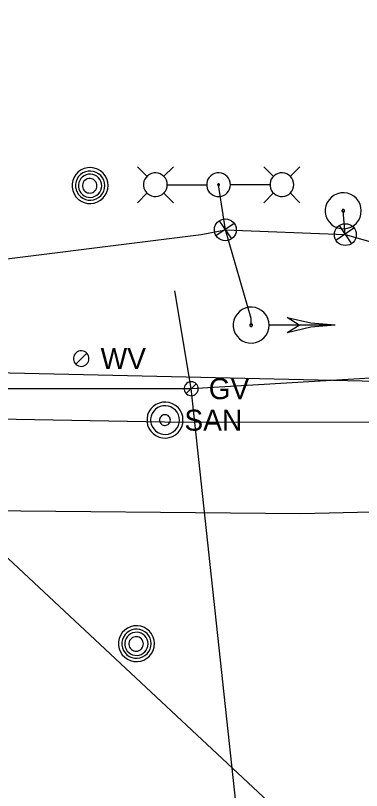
# Model space of a CAD drawing. Extents: x 600849 to 606371, y 330010 to 403088.
# Drawn here: x 605007.3 to 605070.6, y 349901.2 to 350043.3 of the extents above; entities that cross this region are included whole.
import ezdxf

# ---------------------------------------------------------------- set-up
doc = ezdxf.new("R2010")
doc.units = 0
for name, color, linetype in [('E_LTG', 7, 'Continuous'), ('E_LTG_CID', 7, 'Continuous'), ('E_SIG', 7, 'Continuous'), ('E_SIG_Conduit', 7, 'Continuous'), ('E_UTL_G', 7, 'Continuous'), ('E_UTL_G_UG', 7, 'Continuous'), ('E_UTL_MH', 7, 'Continuous'), ('E_UTL_Overhead', 7, 'Continuous'), ('E_UTL_SAN', 7, 'Continuous'), ('E_UTL_SAN_UG', 7, 'Continuous'), ('E_UTL_W', 7, 'Continuous')]:
    doc.layers.add(name, color=color, linetype=linetype)

# ---------------------------------------------------------------- blocks, each defined once
blk = doc.blocks.new('_U352')
at = {"layer": 'E_SIG'}
for p, q in [((0, 6.1), (0, -6.1)), ((-6.09, 0.4), (6.1, 0.4))]:
    blk.add_line(p, q, dxfattribs=at)
blk.add_circle((0, 0.01), 6.1, dxfattribs=at)
blk = doc.blocks.new('_U353')
at = {"layer": 'E_SIG'}
for p, q in [((0, 6.1), (0, -6.1)), ((-6.09, 0.4), (6.1, 0.4))]:
    blk.add_line(p, q, dxfattribs=at)
blk.add_circle((0, 0.01), 6.1, dxfattribs=at)

msp = doc.modelspace()

# ---------------------------------------------------------------- linework, layer by layer
at = {"layer": 'E_LTG'}
for points in [[(605031.33, 350013.81), (605029.56, 350015.58)], [(605034.38, 350013.81), (605036.16, 350015.58)], [(605054.51, 350013.81), (605052.73, 350015.58)], [(605057.55, 350013.81), (605059.33, 350015.58)], [(605035.03, 350012.28), (605035, 350012.7), (605034.88, 350013.09), (605034.69, 350013.46), (605034.43, 350013.78), (605034.12, 350014.06), (605033.76, 350014.26), (605033.37, 350014.4), (605032.96, 350014.46), (605032.55, 350014.44), (605032.15, 350014.34), (605031.77, 350014.17), (605031.43, 350013.93), (605031.15, 350013.63), (605030.93, 350013.28), (605030.77, 350012.9), (605030.69, 350012.49), (605030.69, 350012.08), (605030.77, 350011.67), (605030.93, 350011.29), (605031.15, 350010.94), (605031.43, 350010.64), (605031.77, 350010.4), (605032.15, 350010.23), (605032.55, 350010.13), (605032.96, 350010.11), (605033.37, 350010.17), (605033.76, 350010.3), (605034.12, 350010.51), (605034.43, 350010.78), (605034.69, 350011.11), (605034.88, 350011.47), (605035, 350011.87), (605035.03, 350012.28)], [(605046.6, 350012.28), (605046.56, 350012.69), (605046.44, 350013.09), (605046.26, 350013.46), (605046, 350013.78), (605045.69, 350014.06), (605045.33, 350014.26), (605044.94, 350014.4), (605044.53, 350014.46), (605044.12, 350014.44), (605043.71, 350014.34), (605043.34, 350014.17), (605043, 350013.93), (605042.71, 350013.63), (605042.49, 350013.28), (605042.34, 350012.9), (605042.26, 350012.49), (605042.26, 350012.08), (605042.34, 350011.67), (605042.49, 350011.29), (605042.71, 350010.94), (605043, 350010.64), (605043.34, 350010.4), (605043.71, 350010.23), (605044.12, 350010.13), (605044.53, 350010.11), (605044.94, 350010.17), (605045.33, 350010.3), (605045.69, 350010.51), (605046, 350010.78), (605046.26, 350011.11), (605046.44, 350011.47), (605046.56, 350011.87), (605046.6, 350012.28)], [(605058.2, 350012.28), (605058.16, 350012.69), (605058.05, 350013.09), (605057.86, 350013.46), (605057.6, 350013.78), (605057.29, 350014.06), (605056.93, 350014.26), (605056.54, 350014.4), (605056.13, 350014.46), (605055.72, 350014.44), (605055.32, 350014.34), (605054.94, 350014.17), (605054.6, 350013.93), (605054.32, 350013.63), (605054.09, 350013.28), (605053.94, 350012.9), (605053.86, 350012.49), (605053.86, 350012.08), (605053.94, 350011.67), (605054.09, 350011.29), (605054.32, 350010.94), (605054.6, 350010.64), (605054.94, 350010.4), (605055.32, 350010.23), (605055.72, 350010.13), (605056.13, 350010.11), (605056.54, 350010.17), (605056.93, 350010.3), (605057.29, 350010.51), (605057.6, 350010.78), (605057.86, 350011.11), (605058.05, 350011.47), (605058.16, 350011.87), (605058.2, 350012.28)], [(605035.07, 350012.28), (605042.25, 350012.28)], [(605044.59, 350012.28), (605044.59, 350012.31), (605044.58, 350012.34), (605044.56, 350012.37), (605044.55, 350012.4), (605044.52, 350012.42), (605044.49, 350012.43), (605044.46, 350012.44), (605044.43, 350012.45), (605044.4, 350012.45), (605044.37, 350012.44), (605044.34, 350012.43), (605044.32, 350012.41), (605044.29, 350012.39), (605044.28, 350012.36), (605044.27, 350012.33), (605044.26, 350012.3), (605044.26, 350012.27), (605044.27, 350012.24), (605044.28, 350012.21), (605044.29, 350012.18), (605044.32, 350012.16), (605044.34, 350012.14), (605044.37, 350012.13), (605044.4, 350012.12), (605044.43, 350012.12), (605044.46, 350012.12), (605044.49, 350012.13), (605044.52, 350012.15), (605044.55, 350012.17), (605044.56, 350012.19), (605044.58, 350012.22), (605044.59, 350012.25), (605044.59, 350012.28)], [(605053.82, 350012.28), (605046.64, 350012.28)], [(605031.33, 350010.76), (605029.56, 350008.98)], [(605034.38, 350010.76), (605036.16, 350008.98)], [(605054.51, 350010.76), (605052.73, 350008.98)], [(605057.55, 350010.76), (605059.33, 350008.98)]]:
    msp.add_lwpolyline(points, dxfattribs=at)
at = {"layer": 'E_LTG_CID'}
msp.add_lwpolyline([(605045.68, 350004), (605044.42, 350012.28)], dxfattribs=at)
at = {"layer": 'E_SIG'}
for points in [[(605070.57, 350007.49), (605070.51, 350008.12), (605070.33, 350008.72), (605070.05, 350009.28), (605069.66, 350009.77), (605069.18, 350010.18), (605068.64, 350010.5), (605068.05, 350010.7), (605067.43, 350010.79), (605066.8, 350010.76), (605066.19, 350010.61), (605065.62, 350010.35), (605065.11, 350009.99), (605064.68, 350009.53), (605064.34, 350009.01), (605064.1, 350008.42), (605063.98, 350007.81), (605063.98, 350007.18), (605064.1, 350006.56), (605064.34, 350005.98), (605064.68, 350005.45), (605065.11, 350005), (605065.62, 350004.64), (605066.19, 350004.38), (605066.8, 350004.23), (605067.43, 350004.2), (605068.05, 350004.29), (605068.64, 350004.49), (605069.18, 350004.81), (605069.66, 350005.22), (605070.05, 350005.71), (605070.33, 350006.27), (605070.51, 350006.87), (605070.57, 350007.49)], [(605067.52, 350007.49), (605067.52, 350007.54), (605067.5, 350007.59), (605067.48, 350007.63), (605067.45, 350007.67), (605067.42, 350007.7), (605067.37, 350007.72), (605067.33, 350007.74), (605067.28, 350007.75), (605067.23, 350007.74), (605067.19, 350007.73), (605067.14, 350007.71), (605067.1, 350007.69), (605067.07, 350007.65), (605067.05, 350007.61), (605067.03, 350007.57), (605067.02, 350007.52), (605067.02, 350007.47), (605067.03, 350007.42), (605067.05, 350007.38), (605067.07, 350007.34), (605067.1, 350007.3), (605067.14, 350007.28), (605067.19, 350007.26), (605067.23, 350007.24), (605067.28, 350007.24), (605067.33, 350007.25), (605067.37, 350007.26), (605067.42, 350007.29), (605067.45, 350007.32), (605067.48, 350007.36), (605067.5, 350007.4), (605067.52, 350007.45), (605067.52, 350007.49)], [(605053.7, 349986.52), (605053.64, 349987.14), (605053.46, 349987.75), (605053.18, 349988.3), (605052.79, 349988.8), (605052.31, 349989.21), (605051.77, 349989.52), (605051.18, 349989.73), (605050.56, 349989.82), (605049.93, 349989.79), (605049.32, 349989.64), (605048.75, 349989.38), (605048.24, 349989.01), (605047.81, 349988.56), (605047.47, 349988.03), (605047.23, 349987.45), (605047.12, 349986.83), (605047.12, 349986.21), (605047.23, 349985.59), (605047.47, 349985.01), (605047.81, 349984.48), (605048.24, 349984.03), (605048.75, 349983.66), (605049.32, 349983.4), (605049.93, 349983.25), (605050.56, 349983.22), (605051.18, 349983.31), (605051.77, 349983.52), (605052.31, 349983.83), (605052.79, 349984.24), (605053.18, 349984.74), (605053.46, 349985.29), (605053.64, 349985.9), (605053.7, 349986.52)], [(605059.2, 349986.52), (605057, 349987.9)], [(605065.8, 349986.52), (605061.35, 349986.87), (605057, 349987.89)], [(605050.65, 349986.52), (605050.65, 349986.57), (605050.64, 349986.61), (605050.61, 349986.66), (605050.58, 349986.69), (605050.55, 349986.73), (605050.51, 349986.75), (605050.46, 349986.76), (605050.41, 349986.77), (605050.36, 349986.77), (605050.32, 349986.76), (605050.27, 349986.74), (605050.24, 349986.71), (605050.2, 349986.68), (605050.18, 349986.64), (605050.16, 349986.59), (605050.15, 349986.54), (605050.15, 349986.5), (605050.16, 349986.45), (605050.18, 349986.4), (605050.2, 349986.36), (605050.24, 349986.33), (605050.27, 349986.3), (605050.32, 349986.28), (605050.36, 349986.27), (605050.41, 349986.27), (605050.46, 349986.27), (605050.51, 349986.29), (605050.55, 349986.31), (605050.58, 349986.35), (605050.61, 349986.38), (605050.64, 349986.43), (605050.65, 349986.47), (605050.65, 349986.52)], [(605065.8, 349986.52), (605053.76, 349986.52)], [(605065.8, 349986.52), (605061.35, 349986.17), (605057, 349985.14)], [(605057, 349985.15), (605059.2, 349986.52)]]:
    msp.add_lwpolyline(points, dxfattribs=at)
at = {"layer": 'E_SIG_Conduit'}
for points in [[(605067.59, 350003.14), (605067.27, 350007.49)], [(604992.92, 349997.12), (605041.26, 350003.17), (605045.68, 350004), (605067.59, 350003.14), (605103.15, 349993.06), (605106.99, 349992.73)], [(605050.4, 349986.52), (605050.41, 349987.77), (605045.68, 350004)]]:
    msp.add_lwpolyline(points, dxfattribs=at)
at = {"layer": 'E_UTL_G'}
for points in [[(605040.71, 349974.87), (605040.68, 349975.11), (605040.62, 349975.34), (605040.5, 349975.56), (605040.35, 349975.75), (605040.17, 349975.91), (605039.96, 349976.03), (605039.73, 349976.11), (605039.48, 349976.15), (605039.24, 349976.14), (605039, 349976.08), (605038.78, 349975.98), (605038.58, 349975.83), (605038.42, 349975.66), (605038.28, 349975.45), (605038.19, 349975.23), (605038.15, 349974.99), (605038.15, 349974.74), (605038.19, 349974.5), (605038.28, 349974.28), (605038.42, 349974.07), (605038.58, 349973.9), (605038.78, 349973.75), (605039, 349973.65), (605039.24, 349973.59), (605039.48, 349973.58), (605039.73, 349973.62), (605039.96, 349973.7), (605040.17, 349973.82), (605040.35, 349973.98), (605040.5, 349974.17), (605040.62, 349974.39), (605040.68, 349974.62), (605040.71, 349974.87)], [(605038.52, 349973.96), (605040.33, 349975.77)]]:
    msp.add_lwpolyline(points, dxfattribs=at)
at = {"layer": 'E_UTL_G_UG'}
for points in [[(605039.42, 349974.87), (605036.44, 349992.81)], [(605039.42, 349974.87), (605114.39, 349979.35)], [(604995.37, 349952.58), (604995.37, 349974.87), (605039.42, 349974.87)], [(605053.61, 349842.94), (605039.42, 349974.87)], [(604797.56, 349955.68), (604807.59, 349955.39), (604836.44, 349954.33), (604859.25, 349954.54), (604937.34, 349952.88), (604995.37, 349952.58), (605059.43, 349951.99), (605132.59, 349953.68), (605169.29, 349952.69)]]:
    msp.add_lwpolyline(points, dxfattribs=at)
at = {"layer": 'E_UTL_MH'}
for points in [[(605024.21, 350012.12), (605024.15, 350012.75), (605023.97, 350013.35), (605023.68, 350013.91), (605023.29, 350014.4), (605022.82, 350014.81), (605022.28, 350015.13), (605021.68, 350015.33), (605021.06, 350015.42), (605020.44, 350015.39), (605019.83, 350015.24), (605019.26, 350014.98), (605018.74, 350014.62), (605018.31, 350014.16), (605017.97, 350013.64), (605017.74, 350013.05), (605017.62, 350012.44), (605017.62, 350011.81), (605017.74, 350011.19), (605017.97, 350010.61), (605018.31, 350010.08), (605018.74, 350009.63), (605019.26, 350009.27), (605019.83, 350009.01), (605020.44, 350008.86), (605021.06, 350008.83), (605021.68, 350008.92), (605022.28, 350009.12), (605022.82, 350009.44), (605023.29, 350009.85), (605023.68, 350010.34), (605023.97, 350010.9), (605024.15, 350011.5), (605024.21, 350012.12)], [(605023.59, 350012.12), (605023.54, 350012.63), (605023.4, 350013.11), (605023.17, 350013.57), (605022.85, 350013.97), (605022.47, 350014.3), (605022.03, 350014.55), (605021.54, 350014.72), (605021.04, 350014.79), (605020.53, 350014.77), (605020.04, 350014.65), (605019.58, 350014.44), (605019.16, 350014.14), (605018.81, 350013.77), (605018.53, 350013.35), (605018.35, 350012.87), (605018.25, 350012.37), (605018.25, 350011.87), (605018.35, 350011.37), (605018.53, 350010.89), (605018.81, 350010.47), (605019.16, 350010.1), (605019.58, 350009.8), (605020.04, 350009.59), (605020.53, 350009.47), (605021.04, 350009.45), (605021.54, 350009.52), (605022.03, 350009.68), (605022.47, 350009.94), (605022.85, 350010.27), (605023.17, 350010.67), (605023.4, 350011.12), (605023.54, 350011.61), (605023.59, 350012.12)], [(605023.03, 350012.09), (605022.99, 350012.49), (605022.87, 350012.88), (605022.69, 350013.24), (605022.44, 350013.56), (605022.13, 350013.83), (605021.78, 350014.03), (605021.4, 350014.16), (605021, 350014.22), (605020.6, 350014.2), (605020.2, 350014.1), (605019.83, 350013.93), (605019.5, 350013.7), (605019.22, 350013.41), (605019.01, 350013.07), (605018.86, 350012.69), (605018.78, 350012.29), (605018.78, 350011.89), (605018.86, 350011.49), (605019.01, 350011.12), (605019.22, 350010.78), (605019.5, 350010.48), (605019.83, 350010.25), (605020.2, 350010.08), (605020.6, 350009.98), (605021, 350009.96), (605021.4, 350010.02), (605021.78, 350010.15), (605022.13, 350010.36), (605022.44, 350010.62), (605022.69, 350010.94), (605022.87, 350011.3), (605022.99, 350011.69), (605023.03, 350012.09)], [(605022.17, 350012.08), (605022.15, 350012.33), (605022.08, 350012.57), (605021.96, 350012.8), (605021.8, 350012.99), (605021.61, 350013.16), (605021.39, 350013.29), (605021.15, 350013.37), (605020.9, 350013.41), (605020.65, 350013.39), (605020.4, 350013.33), (605020.17, 350013.23), (605019.97, 350013.08), (605019.79, 350012.9), (605019.66, 350012.69), (605019.56, 350012.45), (605019.51, 350012.2), (605019.51, 350011.95), (605019.56, 350011.7), (605019.66, 350011.47), (605019.79, 350011.25), (605019.97, 350011.07), (605020.17, 350010.92), (605020.4, 350010.82), (605020.65, 350010.76), (605020.9, 350010.75), (605021.15, 350010.78), (605021.39, 350010.86), (605021.61, 350010.99), (605021.8, 350011.16), (605021.96, 350011.36), (605022.08, 350011.58), (605022.15, 350011.82), (605022.17, 350012.08)], [(605032.7, 349928.1), (605032.64, 349928.72), (605032.47, 349929.32), (605032.18, 349929.88), (605031.79, 349930.37), (605031.32, 349930.78), (605030.77, 349931.1), (605030.18, 349931.3), (605029.56, 349931.39), (605028.93, 349931.36), (605028.32, 349931.21), (605027.75, 349930.95), (605027.24, 349930.59), (605026.81, 349930.14), (605026.47, 349929.61), (605026.24, 349929.03), (605026.12, 349928.41), (605026.12, 349927.78), (605026.24, 349927.17), (605026.47, 349926.58), (605026.81, 349926.06), (605027.24, 349925.6), (605027.75, 349925.24), (605028.32, 349924.98), (605028.93, 349924.83), (605029.56, 349924.8), (605030.18, 349924.89), (605030.77, 349925.09), (605031.32, 349925.41), (605031.79, 349925.82), (605032.18, 349926.31), (605032.47, 349926.87), (605032.64, 349927.47), (605032.7, 349928.1)], [(605032.09, 349928.09), (605032.04, 349928.6), (605031.9, 349929.09), (605031.66, 349929.54), (605031.35, 349929.94), (605030.96, 349930.27), (605030.52, 349930.53), (605030.04, 349930.69), (605029.54, 349930.77), (605029.03, 349930.74), (605028.53, 349930.62), (605028.07, 349930.41), (605027.66, 349930.11), (605027.31, 349929.75), (605027.03, 349929.32), (605026.84, 349928.85), (605026.75, 349928.35), (605026.75, 349927.84), (605026.84, 349927.34), (605027.03, 349926.87), (605027.31, 349926.44), (605027.66, 349926.07), (605028.07, 349925.77), (605028.53, 349925.56), (605029.03, 349925.44), (605029.54, 349925.42), (605030.04, 349925.49), (605030.52, 349925.66), (605030.96, 349925.91), (605031.35, 349926.24), (605031.66, 349926.64), (605031.9, 349927.1), (605032.04, 349927.59), (605032.09, 349928.09)], [(605031.52, 349928.06), (605031.49, 349928.47), (605031.37, 349928.85), (605031.19, 349929.21), (605030.94, 349929.53), (605030.63, 349929.8), (605030.28, 349930), (605029.9, 349930.13), (605029.5, 349930.19), (605029.09, 349930.17), (605028.7, 349930.08), (605028.33, 349929.91), (605028, 349929.67), (605027.72, 349929.38), (605027.5, 349929.04), (605027.35, 349928.66), (605027.28, 349928.27), (605027.28, 349927.86), (605027.35, 349927.46), (605027.5, 349927.09), (605027.72, 349926.75), (605028, 349926.45), (605028.33, 349926.22), (605028.7, 349926.05), (605029.09, 349925.96), (605029.5, 349925.94), (605029.9, 349925.99), (605030.28, 349926.13), (605030.63, 349926.33), (605030.94, 349926.59), (605031.19, 349926.91), (605031.37, 349927.27), (605031.49, 349927.66), (605031.52, 349928.06)], [(605030.67, 349928.05), (605030.64, 349928.3), (605030.57, 349928.54), (605030.46, 349928.77), (605030.3, 349928.97), (605030.11, 349929.13), (605029.89, 349929.26), (605029.65, 349929.34), (605029.4, 349929.38), (605029.15, 349929.37), (605028.9, 349929.31), (605028.67, 349929.2), (605028.46, 349929.05), (605028.29, 349928.87), (605028.15, 349928.66), (605028.06, 349928.42), (605028.01, 349928.17), (605028.01, 349927.92), (605028.06, 349927.67), (605028.15, 349927.44), (605028.29, 349927.22), (605028.46, 349927.04), (605028.67, 349926.89), (605028.9, 349926.79), (605029.15, 349926.73), (605029.4, 349926.72), (605029.65, 349926.75), (605029.89, 349926.84), (605030.11, 349926.96), (605030.3, 349927.13), (605030.46, 349927.33), (605030.57, 349927.55), (605030.64, 349927.8), (605030.67, 349928.05)]]:
    msp.add_lwpolyline(points, dxfattribs=at)
at = {"layer": 'E_UTL_Overhead'}
for points in [[(603181.1, 350033.93), (603327.14, 350030.65), (603489.53, 350051.02), (603697.71, 350051.22), (603796.19, 350042.83), (603984.49, 350028.4), (604130.29, 350016.64), (604350.17, 349999.98), (604453.05, 349992.41), (604555.19, 349985.21), (604652.23, 349982.52), (604745.22, 349980.5), (604854.74, 349979.72), (604968.56, 349978.6), (605154.01, 349974.42)], [(604968.56, 349978.6), (605140.32, 349817.89)]]:
    msp.add_lwpolyline(points, dxfattribs=at)
at = {"layer": 'E_UTL_SAN'}
for points in [[(605037.92, 349969.11), (605037.86, 349969.74), (605037.68, 349970.34), (605037.4, 349970.9), (605037.01, 349971.39), (605036.53, 349971.8), (605035.99, 349972.11), (605035.4, 349972.32), (605034.78, 349972.41), (605034.15, 349972.38), (605033.54, 349972.23), (605032.97, 349971.97), (605032.46, 349971.61), (605032.03, 349971.15), (605031.69, 349970.62), (605031.45, 349970.04), (605031.34, 349969.42), (605031.34, 349968.8), (605031.45, 349968.18), (605031.69, 349967.6), (605032.03, 349967.07), (605032.46, 349966.62), (605032.97, 349966.25), (605033.54, 349965.99), (605034.15, 349965.84), (605034.78, 349965.81), (605035.4, 349965.9), (605035.99, 349966.11), (605036.53, 349966.42), (605037.01, 349966.83), (605037.4, 349967.33), (605037.68, 349967.88), (605037.86, 349968.49), (605037.92, 349969.11)], [(605037.26, 349969.11), (605037.21, 349969.61), (605037.07, 349970.09), (605036.84, 349970.54), (605036.53, 349970.93), (605036.15, 349971.26), (605035.72, 349971.51), (605035.24, 349971.68), (605034.75, 349971.75), (605034.24, 349971.72), (605033.76, 349971.61), (605033.3, 349971.4), (605032.89, 349971.11), (605032.55, 349970.74), (605032.27, 349970.32), (605032.09, 349969.85), (605031.99, 349969.36), (605031.99, 349968.86), (605032.09, 349968.37), (605032.27, 349967.9), (605032.55, 349967.48), (605032.89, 349967.12), (605033.3, 349966.82), (605033.76, 349966.62), (605034.24, 349966.5), (605034.75, 349966.47), (605035.24, 349966.55), (605035.72, 349966.71), (605036.15, 349966.96), (605036.53, 349967.29), (605036.84, 349967.68), (605037.07, 349968.13), (605037.21, 349968.61), (605037.26, 349969.11)], [(605035.61, 349969.11), (605035.59, 349969.3), (605035.54, 349969.48), (605035.45, 349969.65), (605035.34, 349969.79), (605035.19, 349969.92), (605035.03, 349970.01), (605034.85, 349970.07), (605034.67, 349970.1), (605034.48, 349970.09), (605034.3, 349970.05), (605034.13, 349969.97), (605033.97, 349969.86), (605033.84, 349969.72), (605033.74, 349969.56), (605033.67, 349969.39), (605033.64, 349969.21), (605033.64, 349969.02), (605033.67, 349968.83), (605033.74, 349968.66), (605033.84, 349968.5), (605033.97, 349968.36), (605034.13, 349968.25), (605034.3, 349968.18), (605034.48, 349968.13), (605034.67, 349968.12), (605034.85, 349968.15), (605035.03, 349968.21), (605035.19, 349968.3), (605035.34, 349968.43), (605035.45, 349968.58), (605035.54, 349968.74), (605035.59, 349968.92), (605035.61, 349969.11)]]:
    msp.add_lwpolyline(points, dxfattribs=at)
at = {"layer": 'E_UTL_SAN_UG'}
for p, q in [((604736.58, 349974.22), (605034.55, 349968.79)), ((605034.55, 349968.79), (605091.22, 349968.71))]:
    msp.add_line(p, q, dxfattribs=at)
at = {"layer": 'E_UTL_W'}
for points in [[(605020.7, 349980.39), (605020.68, 349980.66), (605020.6, 349980.92), (605020.48, 349981.16), (605020.31, 349981.37), (605020.1, 349981.55), (605019.87, 349981.68), (605019.61, 349981.77), (605019.34, 349981.81), (605019.07, 349981.8), (605018.81, 349981.73), (605018.56, 349981.62), (605018.34, 349981.46), (605018.16, 349981.27), (605018.01, 349981.04), (605017.91, 349980.79), (605017.86, 349980.52), (605017.86, 349980.25), (605017.91, 349979.98), (605018.01, 349979.73), (605018.16, 349979.5), (605018.34, 349979.31), (605018.56, 349979.15), (605018.81, 349979.04), (605019.07, 349978.97), (605019.34, 349978.96), (605019.61, 349979), (605019.87, 349979.09), (605020.1, 349979.22), (605020.31, 349979.4), (605020.48, 349979.62), (605020.6, 349979.86), (605020.68, 349980.12), (605020.7, 349980.39)], [(605018.27, 349979.38), (605020.29, 349981.39)]]:
    msp.add_lwpolyline(points, dxfattribs=at)

# ---------------------------------------------------------------- block references
at = {"layer": 'E_SIG_Conduit', "xscale": 0.32808333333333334, "yscale": 0.3280833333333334, "rotation": 34.193210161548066}
for name, p in [('_U352', (605045.68, 350004)), ('_U353', (605067.64, 350003.12))]:
    msp.add_blockref(name, p, dxfattribs=at)

# ---------------------------------------------------------------- texts
at = {"layer": 'E_UTL_G'}
msp.add_text('GV', height=3.85, dxfattribs=at).set_placement((605042.63, 349972.94))
at = {"layer": 'E_UTL_SAN'}
msp.add_text('SAN', height=3.849, dxfattribs=at).set_placement((605038.18, 349967.17))
at = {"layer": 'E_UTL_W'}
msp.add_text('WV', height=3.85, dxfattribs=at).set_placement((605022.84, 349978.46))

doc.saveas('drawing.dxf')
